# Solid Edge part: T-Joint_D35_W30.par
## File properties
Author: fknapp
Template: iso metric part.par
Last saved by: fknapp
Revision: 155
Application: Solid Edge
Username: fknapp
Genauigkeit: 0,990
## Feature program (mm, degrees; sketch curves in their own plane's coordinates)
sketch for "unnamed Protrusion 1" plane through (0, 0, 0) normal (0, 0, 1) x-axis (1, 0, 0)
  line (17.4, 17.4) -> (-17.4, 17.4)
  line (-17.4, 17.4) -> (-17.4, -17.4)
  line (-17.4, -17.4) -> (17.4, -17.4)
  line (17.4, -17.4) -> (17.4, 17.4)
  dimension (linear) = 17.4
  dimension (linear) = 17.4
extrude "unnamed Protrusion 1" add finite 16 along +normal
chamfer "Fase_2" setback 15  SetBackValue2 = 30 deg
sketch for "Bohrung_1" plane through (0, -13.2441, 8.1983) normal (0, -0.866025, 0.5) x-axis (1, 0, 0)
  hole centre (0, 0.7221) bore radius 6.25
hole "Bohrung_1" diameter 12.5 through  CounterSinkAngle = 90 deg
fillet "Verrundung_2" radius 17.4
sketch for "Bohrung_2" plane through (-0.1, 6.1215, 16) normal (0, 0, 1) x-axis (1, 0, 0)
hole "Bohrung_2" diameter 6.2 through  CounterSinkAngle = 90 deg
sketch for "unnamed Hole 1" plane through (-0.1, 6.1215, 16) normal (0, 0, 1) x-axis (1, 0, 0)
hole "unnamed Hole 1" through
pattern "unnamed Pattern 1" of "Bohrung_2", "unnamed Hole 1"
fillet "Verrundung_4" radius 0.5
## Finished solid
Body 1: solid body, 12 faces, 19 edges, 6 vertices.
  Faces by surface: cylinder 4, cone 3, plane 3, torus 2
  Edges by curve: circle 12, intersection 3, ellipse 2, line 2
Bounding box of the edges (mm; curved faces can reach further): 34.800 x 34.800 x 16.000, from (-17.4, -17.4, 0) to (17.4, 17.4, 16).
Cylindrical faces by radius (mm): R3.1 x2, R6.25 x1, R17.4 x1
Conical faces (half-angle, radius in mm at the cone's reference point): 45 deg R6 x2, 45 deg R9 x1
Toroidal faces (ring radius, tube radius in mm): R16.9 r0.5 x2
Planar faces by outward normal: +z 1, -z 1, oblique 1
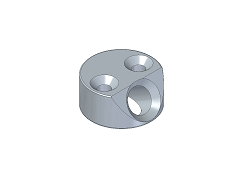
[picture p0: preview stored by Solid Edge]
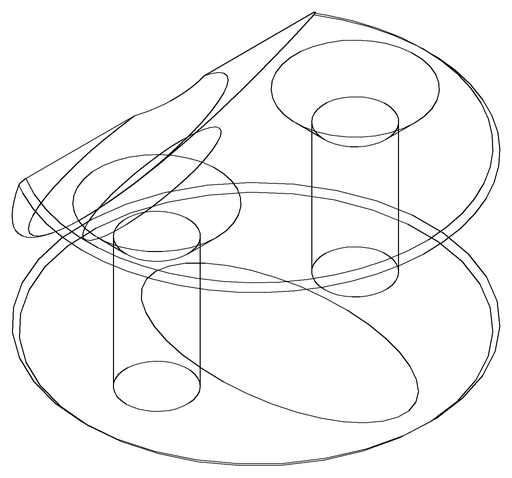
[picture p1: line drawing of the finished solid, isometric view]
